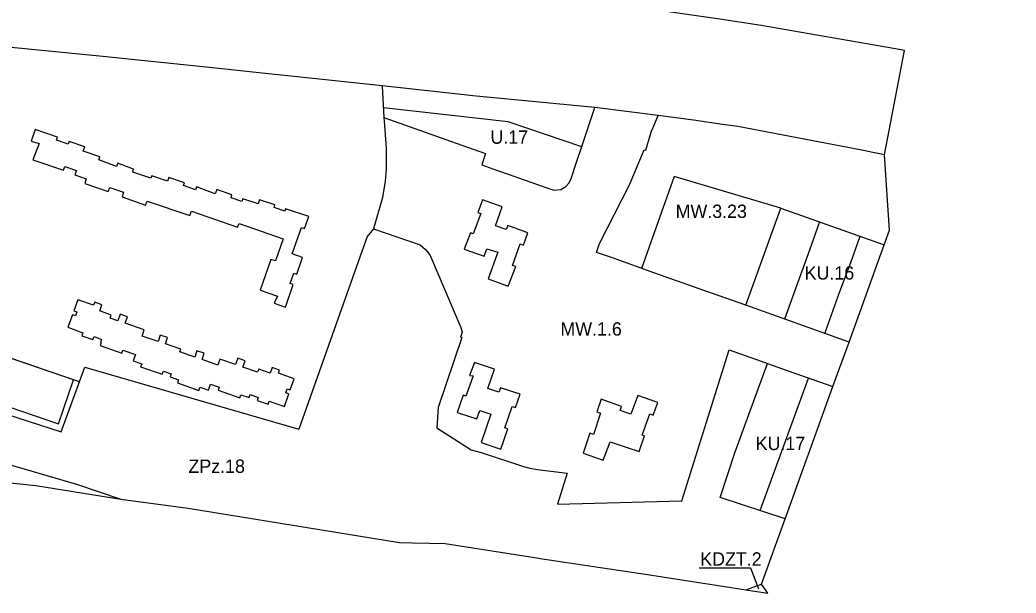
# Model space of a CAD drawing. Extents: x 7428239 to 7429836, y 5549133 to 5550853.
# Drawn here: x 7429012.7 to 7429386.4, y 5549132.9 to 5549348.1 of the extents above; entities that cross this region are included whole.
import ezdxf

# ---------------------------------------------------------------- set-up
doc = ezdxf.new("R2010")
doc.units = 0
for name, color, linetype in [('LIN_linie rozgraniczające', 7, 'Continuous'), ('LIN_nieprzekraczalna linia zabudowy', 7, 'Continuous'), ('LIN_obowiązująca linia zabudowy', 7, 'Continuous'), ('TXT_Oznaczenia Przeznaczenia', 7, 'Continuous')]:
    doc.layers.add(name, color=color, linetype=linetype)

msp = doc.modelspace()

# ---------------------------------------------------------------- linework, layer by layer
at = {"layer": 'LIN_linie rozgraniczające'}
for p, q in [((7429337, 5549297.44), (7429344.52, 5549336.6)), ((7429037.02, 5549217.7), (7429117.34, 5549194.52)), ((7429308.51, 5549185.02), (7429317.72, 5549210.49)), ((7429305.53, 5549176.78), (7429307.8, 5549183.06)), ((7429307.8, 5549183.06), (7429308.51, 5549185.02)), ((7428990.9, 5549176.27), (7429018.7, 5549173.26)), ((7429302.73, 5549169.04), (7429305.53, 5549176.78)), ((7429018.7, 5549173.26), (7429050.53, 5549168.23)), ((7429050.53, 5549168.23), (7429075.84, 5549164.77)), ((7429299.75, 5549160.81), (7429275.37, 5549168.78)), ((7429075.84, 5549164.77), (7429155.07, 5549151.87)), ((7429155.07, 5549151.87), (7429160.01, 5549151.77)), ((7429160.01, 5549151.77), (7429166.21, 5549151.65)), ((7429166.21, 5549151.65), (7429172.25, 5549151.52)), ((7429172.25, 5549151.52), (7429207.4, 5549145.99)), ((7429207.4, 5549145.99), (7429207.91, 5549145.92)), ((7429207.91, 5549145.92), (7429248.18, 5549139.94))]:
    msp.add_line(p, q, dxfattribs=at)
for points in [[(7429344.52, 5549336.6), (7429341.17, 5549337.18), (7429290.81, 5549346), (7429274.35, 5549348.49), (7429256.87, 5549351.01), (7429254.51, 5549351.36), (7429258.8, 5549358.75), (7429259.61, 5549360.15), (7429264.22, 5549368.09), (7429278.6, 5549365.24), (7429295.04, 5549361.98), (7429295.54, 5549363.92), (7429315.32, 5549440.78), (7429319.9, 5549459.86), (7429321.58, 5549466.87), (7429336.38, 5549492.35), (7429370.03, 5549550.3), (7429374.84, 5549558.59), (7429386.42, 5549553.65)], [(7429123.78, 5549325.92), (7429105.9, 5549327.83), (7429084.89, 5549330.08), (7429043.79, 5549334.28), (7428985.21, 5549340.08), (7428947.39, 5549343.91), (7428938.83, 5549344.78)], [(7429337, 5549297.44), (7429332.62, 5549298.33), (7429329.14, 5549299.04), (7429282.03, 5549308.03), (7429276.33, 5549308.86), (7429265.34, 5549310.4), (7429252.17, 5549312.23), (7429228.36, 5549315.14), (7429214.05, 5549316.55), (7429182.66, 5549319.63), (7429181.64, 5549319.74), (7429148.58, 5549323.27), (7429123.78, 5549325.92)], [(7429148.58, 5549323.27), (7429148.58, 5549323.16), (7429149.27, 5549311.43), (7429149.44, 5549308.46), (7429150.06, 5549299.76), (7429150.06, 5549297.36), (7429150.06, 5549296.34), (7429150.07, 5549292.07), (7429149.73, 5549287.57), (7429148.76, 5549281.42), (7429145.4, 5549269.68), (7429142.91, 5549266.77), (7429131.19, 5549233.67), (7429117.34, 5549194.52)], [(7429149.27, 5549311.43), (7429176.38, 5549301.85), (7429187.4, 5549297.96), (7429185.96, 5549293.63), (7429190.14, 5549292.15), (7429195.46, 5549290.25), (7429203.97, 5549287.27), (7429210.75, 5549284.91), (7429212.94, 5549284.2), (7429215.64, 5549284.44), (7429217.56, 5549285.55), (7429218.69, 5549286.81), (7429219.44, 5549288.2), (7429221.67, 5549295.01), (7429223.37, 5549300.22), (7429226.23, 5549308.76), (7429228.36, 5549315.14)], [(7429323.76, 5549227.18), (7429284.98, 5549240.96), (7429267.5, 5549247.17), (7429250.95, 5549253.04), (7429234.98, 5549258.71), (7429229, 5549260.83), (7429230.18, 5549264.19), (7429241.43, 5549286.19), (7429246.85, 5549299.35), (7429247.48, 5549299.16), (7429249.72, 5549306.85), (7429249.92, 5549306.79), (7429252.17, 5549312.23)], [(7429334.21, 5549256.05), (7429336.95, 5549263.62), (7429338.96, 5549269.18), (7429337, 5549297.44)], [(7429284.98, 5549240.96), (7429298.17, 5549277.43), (7429336.95, 5549263.62)], [(7429145.4, 5549269.68), (7429162.91, 5549263.63), (7429164.87, 5549261.96), (7429165.95, 5549260.54), (7429166.62, 5549259.64), (7429178.14, 5549232.58), (7429178.6, 5549230.81), (7429178, 5549228.97), (7429178.54, 5549228.83), (7429169.62, 5549202.6), (7429169.11, 5549195.01), (7429182.05, 5549186.76), (7429185.71, 5549185.66), (7429201.56, 5549180.43), (7429204, 5549179.77), (7429206.89, 5549179.38), (7429217.97, 5549177.89), (7429214.33, 5549166.35), (7429260.97, 5549167.51), (7429278.8, 5549224.2), (7429290.77, 5549219.98), (7429293.13, 5549219.15), (7429300.96, 5549216.39), (7429307.69, 5549213.94), (7429317.72, 5549210.49)], [(7429317.72, 5549210.49), (7429323.76, 5549227.18), (7429334.21, 5549256.05)], [(7428766.32, 5549249.09), (7428785.3, 5549244.05), (7428861.41, 5549222.78), (7428928.37, 5549203.85), (7428940.4, 5549200.46), (7429011.61, 5549180.33), (7429033.89, 5549173.88), (7429050.53, 5549168.23)], [(7428782.01, 5549249.94), (7428786.93, 5549248.73), (7428863.9, 5549229.77), (7428867.22, 5549239.06), (7428926.12, 5549220.34), (7428972.45, 5549212.5), (7428992.52, 5549205.27), (7428995.96, 5549203.93), (7428999.99, 5549202.63), (7429003.28, 5549201.44), (7429028.18, 5549193.43), (7429037.02, 5549217.7)], [(7429035.03, 5549212.23), (7429024.75, 5549215.75), (7429015, 5549219.08), (7429007.34, 5549221.7), (7429007.51, 5549223), (7429007.17, 5549224.29), (7429006.37, 5549225.34), (7429005.22, 5549226), (7429000.77, 5549227.53), (7428991.03, 5549230.85), (7428984.39, 5549233.12), (7428982.97, 5549232.69), (7428977.88, 5549227.09), (7428972.45, 5549212.5)], [(7429275.37, 5549168.78), (7429281.01, 5549185.98), (7429293.13, 5549219.15)], [(7429293.28, 5549132.94), (7429290.87, 5549136.27), (7429299.75, 5549160.81), (7429302.73, 5549169.04)], [(7429248.18, 5549139.94), (7429279.5, 5549135.06), (7429285.08, 5549134.2), (7429293.28, 5549132.94)], [(7429285.08, 5549134.2), (7429290.87, 5549136.27)]]:
    msp.add_lwpolyline(points, dxfattribs=at)
at = {"layer": 'LIN_nieprzekraczalna linia zabudowy'}
for points in [[(7429223.45, 5549300.46), (7429195.9, 5549309.84), (7429149.05, 5549315.13)], [(7429298.17, 5549277.43), (7429258.17, 5549289.26), (7429245.94, 5549254.82)], [(7429312.71, 5549272.25), (7429308.9, 5549261.63), (7429304.87, 5549250.63), (7429299.53, 5549235.79)], [(7429314.7, 5549230.4), (7429320.35, 5549246.08), (7429324.38, 5549257.08), (7429327.88, 5549266.85)], [(7429032.79, 5549213), (7429007.34, 5549221.7), (7429007.51, 5549223), (7429007.17, 5549224.29), (7429006.37, 5549225.34), (7429005.22, 5549226), (7428984.39, 5549233.12), (7428977, 5549213.56), (7429027.12, 5549196.44), (7429032.79, 5549213)], [(7429290.36, 5549163.88), (7429308.55, 5549213.63)]]:
    msp.add_lwpolyline(points, dxfattribs=at)
at = {"layer": 'LIN_obowiązująca linia zabudowy'}
for points in [[(7429121.08, 5549274.25), (7429112.37, 5549277.2), (7429112.05, 5549276.25), (7429108.02, 5549277.62), (7429108.34, 5549278.62), (7429102.57, 5549280.55), (7429102.04, 5549279.04), (7429096.29, 5549280.97), (7429095.91, 5549279.94), (7429091.9, 5549281.35), (7429092.24, 5549282.41), (7429086.55, 5549284.37), (7429085.97, 5549282.85), (7429078.89, 5549285.41), (7429078.53, 5549284.29), (7429074.09, 5549285.86), (7429074.46, 5549286.94), (7429068.56, 5549288.96), (7429068.01, 5549287.59), (7429062.14, 5549289.5), (7429061.84, 5549288.66), (7429055, 5549290.97), (7429055.35, 5549292.05), (7429049.42, 5549294.26), (7429048.98, 5549293.09), (7429042.26, 5549295.61), (7429042.62, 5549296.62), (7429036.47, 5549298.75), (7429037.03, 5549300.47), (7429031.21, 5549302.46), (7429030.78, 5549301.4), (7429026.44, 5549302.91), (7429026.79, 5549304.06), (7429018.37, 5549306.91), (7429016.96, 5549302.54), (7429019.87, 5549301.64), (7429017.49, 5549295.6), (7429029.07, 5549291.68), (7429029.56, 5549293.09), (7429033.9, 5549291.58), (7429033.32, 5549289.88), (7429037.54, 5549288.45), (7429037, 5549286.63), (7429045.83, 5549283.73), (7429046.44, 5549285.2), (7429051.6, 5549283.44), (7429051.02, 5549281.62), (7429059.84, 5549278.49), (7429060.45, 5549280.1), (7429076.45, 5549274.62), (7429077.06, 5549276.25), (7429094.36, 5549270.25), (7429094.89, 5549271.68), (7429111.43, 5549265.94), (7429108.56, 5549257.64), (7429106.87, 5549258.14), (7429102.86, 5549246.59), (7429109.29, 5549244.35), (7429108.09, 5549241.75), (7429112.3, 5549240.22), (7429115.21, 5549248.77), (7429114.14, 5549249.17), (7429115.48, 5549253.06), (7429116.63, 5549252.69), (7429118.71, 5549258.92), (7429114.83, 5549260.28), (7429118.3, 5549270.1), (7429119.5, 5549269.73)], [(7429186.25, 5549280.6), (7429184.47, 5549275.81), (7429185.67, 5549275.38), (7429182.79, 5549267.75), (7429181.7, 5549268.14), (7429179.42, 5549262.05), (7429186.86, 5549259.38), (7429187.88, 5549262.2), (7429192.03, 5549260.84), (7429188.41, 5549250.87), (7429195.92, 5549248.12), (7429198.71, 5549255.54), (7429197.51, 5549255.95), (7429200.37, 5549264.07), (7429201.68, 5549263.58), (7429203.3, 5549268.12), (7429195.69, 5549270.91), (7429195.13, 5549269.4), (7429191.1, 5549270.81), (7429193.66, 5549277.9)], [(7429058.56, 5549229.39), (7429059.37, 5549231.75), (7429052.19, 5549234.25), (7429053, 5549236.6), (7429050.26, 5549237.57), (7429049.39, 5549235.12), (7429046.56, 5549236.13), (7429046.96, 5549237.27), (7429042.62, 5549238.82), (7429043.47, 5549241.18), (7429040.74, 5549242.17), (7429040.3, 5549240.95), (7429034.41, 5549243.05), (7429032.92, 5549238.91), (7429034.05, 5549238.5), (7429033.51, 5549237), (7429032.38, 5549237.4), (7429030.7, 5549232.69), (7429036.35, 5549230.67), (7429035.94, 5549229.54), (7429040.09, 5549228.06), (7429040.49, 5549229.19), (7429043.32, 5549228.18), (7429042.91, 5549227.05), (7429043.19, 5549226.95), (7429042.8, 5549225.82), (7429050.92, 5549223.01), (7429051.32, 5549224.14), (7429056.04, 5549222.5), (7429055.21, 5549220.14), (7429058.38, 5549219.03), (7429057.98, 5549217.9), (7429066.1, 5549215.07), (7429066.5, 5549216.21), (7429069.43, 5549215.2), (7429069.04, 5549214.06), (7429072.15, 5549212.98), (7429071.76, 5549211.84), (7429079.88, 5549209.03), (7429080.27, 5549210.17), (7429083.39, 5549209.08), (7429084.18, 5549211.34), (7429087.49, 5549210.2), (7429087.09, 5549209.06), (7429095.22, 5549206.25), (7429095.62, 5549207.39), (7429098.73, 5549206.3), (7429099.13, 5549207.44), (7429102.1, 5549206.41), (7429101.71, 5549205.27), (7429105.87, 5549203.83), (7429106.26, 5549204.97), (7429111.93, 5549203), (7429113.57, 5549207.72), (7429112.43, 5549208.12), (7429112.95, 5549209.63), (7429114.09, 5549209.24), (7429115.53, 5549213.4), (7429109.67, 5549215.43), (7429110.1, 5549216.66), (7429107.37, 5549217.62), (7429106.61, 5549215.45), (7429102.27, 5549216.97), (7429101.88, 5549215.85), (7429096.32, 5549217.79), (7429097.14, 5549220.15), (7429094.4, 5549221.11), (7429093.58, 5549218.75), (7429087.73, 5549220.8), (7429086.94, 5549218.53), (7429081.02, 5549220.58), (7429081.84, 5549222.95), (7429079.1, 5549223.9), (7429078.28, 5549221.53), (7429072.7, 5549223.45), (7429073.06, 5549224.49), (7429067.28, 5549226.48), (7429068.1, 5549228.85), (7429065.36, 5549229.8), (7429064.51, 5549227.34)], [(7429176.78, 5549200.74), (7429184.1, 5549198.31), (7429185.18, 5549201.42), (7429189.37, 5549200.06), (7429185.77, 5549189.48), (7429193.11, 5549186.94), (7429195.7, 5549194.54), (7429194.56, 5549194.94), (7429197.32, 5549203.02), (7429198.66, 5549202.57), (7429200.35, 5549207.54), (7429192.99, 5549209.94), (7429192.42, 5549208.34), (7429188.28, 5549209.74), (7429190.72, 5549217.01), (7429183.21, 5549219.44), (7429181.4, 5549214.62), (7429182.68, 5549214.45), (7429179.99, 5549206.81), (7429178.97, 5549207.18)], [(7429251.98, 5549204.5), (7429244.51, 5549207.1), (7429241.94, 5549200.04), (7429237.89, 5549201.44), (7429238.44, 5549203), (7429230.75, 5549205.71), (7429229.12, 5549200.96), (7429230.53, 5549200.47), (7429227.83, 5549192.5), (7429226.47, 5549192.95), (7429224, 5549185.48), (7429231.48, 5549182.77), (7429234.13, 5549189.76), (7429245.03, 5549186.14), (7429247.01, 5549191.95), (7429246.1, 5549192.27), (7429249.01, 5549200.21), (7429250.33, 5549199.73)]]:
    msp.add_lwpolyline(points, close=True, dxfattribs=at)
at = {"layer": 'TXT_Oznaczenia Przeznaczenia'}
msp.add_lwpolyline([(7429267.5, 5549142.46), (7429286.83, 5549142.46), (7429289.75, 5549134.53)], dxfattribs=at)

# ---------------------------------------------------------------- texts
for s, p in [('U.17', (7429189.22, 5549301.57)), ('MW.3.23', (7429258.69, 5549273.75)), ('KU.16', (7429307.1, 5549250.61)), ('MW.1.6', (7429215.47, 5549229.59)), ('KU.17', (7429288.72, 5549186.59)), ('ZPz.18', (7429075.93, 5549178.07)), ('KDZT.2', (7429267.93, 5549143.24))]:
    msp.add_text(s, height=5, dxfattribs=at).set_placement(p)

doc.saveas('drawing.dxf')
